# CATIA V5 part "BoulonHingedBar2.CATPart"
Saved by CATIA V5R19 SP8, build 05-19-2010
Part number: BoulonHingedBar2
Bounding box of the stored display mesh (mm): x -36 to 32, y 992 to 1008, z 492 to 508
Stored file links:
  G:\EU_thinkMotion\CFAO_2010\MMS_groupe3\MMS_groupe3\A reprendre\fovide\fovide\BoulonHingedBar2.CATPart
  C:\Users\Rodger\Desktop\Part11.CATPart
  G:\EU_thinkMotion\CFAO_2010\MMS_groupe3\MMS_groupe3\A reprendre\fovide\fovide\fovide.CATProduct
  G:\EU_thinkMotion\CFAO_2010\MMS_groupe3\MMS_groupe3\A reprendre\fovide\fovide\Hinged Bar 15.CATPart
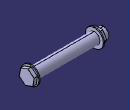
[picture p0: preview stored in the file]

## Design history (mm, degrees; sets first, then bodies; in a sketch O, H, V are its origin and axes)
Parameters
  Diametre = 10 mm
  Longueur = 56 mm
Set1
  DatumSurface1: linked copy from another document
  Point1: linked copy from another document
Body1 (main body)
Body2
  Sketch1 on DatumSurface1, origin (28, 0, 28), H (0, 0, -1), V (0, 1, 0)
    circle A1 centre (-472, 1000) radius 8
    point P1 (-472, 1000)
    reference projected point E1 (-472, 1000) from Point1
    radius A1 = 8 {= Diametre *8/10}
    coincidence: P1 E1
  Pad1: profile Sketch1, direction (1, 0, 0), length 1
  Sketch2 on end face of Pad1, origin (29, 0, 30), H (0, 0, -1), V (0, 1, 0)
    point P1 (-470, 1000)
    point P2 (-467.5061, 993.4593)
    point P3 (-463.0887, 998.8894)
    point P4 (-465.5825, 1005.4301)
    point P5 (-472.4939, 1006.5407)
    point P6 (-476.9113, 1001.1106)
    point P7 (-474.4175, 994.5699)
    point P8 (-465.2974, 996.1744)
    line L1 (-467.5061, 993.4593) -> (-463.0887, 998.8894)
    line L2 (-463.0887, 998.8894) -> (-465.5825, 1005.4301)
    line L3 (-465.5825, 1005.4301) -> (-472.4939, 1006.5407)
    line L4 (-472.4939, 1006.5407) -> (-476.9113, 1001.1106)
    line L5 (-476.9113, 1001.1106) -> (-474.4175, 994.5699)
    line L6 (-474.4175, 994.5699) -> (-467.5061, 993.4593)
    construction line L7 (-470, 1000) -> (-465.2974, 996.1744)
    construction circle A1 centre (-470, 1000) radius 7
    construction arc A2 centre (-476.9113, 1001.1106) radius 7 from (-472.4939, 1006.5407) to (-474.4175, 994.5699) cw
    construction arc A3 centre (-463.0887, 998.8894) radius 7 from (-465.5825, 1005.4301) to (-467.5061, 993.4593) ccw
    reference projected point E1 (-470, 1000) from Point1
    radius A1 = 7 {= Diametre *7/10}
    coincidence: A1 P2, A1 P3, A1 P4, A1 P5, A1 P6, A1 P7, A2 P1, A3 P1, P1 E1
    midpoint: P8 L1
    parallelism: L1 L4
  Pad2: profile Sketch2, direction (1, 0, 0), length 3
  Sketch3 on start face of Pad1, origin (28, 0, 28), H (0, 0, -1), V (0, -1, 0)
    circle A1 centre (-472, -1000) radius 5
    point P1 (-472, -1000)
    reference projected point E1 (-472, -1000) from Point1
    radius A1 = 5 {= Diametre /2}
    coincidence: P1 E1
  Pad3: profile Sketch3, direction (-1, 0, 0), length 56 {= Longueur}
  Sketch4 on end face of Pad3, origin (-28, 0, -52), H (0, 0, -1), V (0, -1, 0)
    circle A1 centre (-552, -1000) radius 8
    point P1 (-552, -1000)
    reference projected point E1 (-552, -1000) from Point1
    radius A1 = 8 {= Diametre *8/10}
    coincidence: P1 E1
  Pad4: profile Sketch4, direction (-1, 0, 0), length 1
  Sketch5 on end face of Pad4, origin (-29, 0, -54), H (0, 0, -1), V (0, -1, 0)
    point P1 (-554, -1000)
    point P2 (-554.0478, -1006.9998)
    point P3 (-547.9619, -1003.5413)
    point P4 (-547.9141, -996.5415)
    point P5 (-553.9522, -993.0002)
    point P6 (-560.0381, -996.4587)
    point P7 (-560.0859, -1003.4585)
    point P8 (-551.0048, -1005.2706)
    line L1 (-554.0478, -1006.9998) -> (-547.9619, -1003.5413)
    line L2 (-547.9619, -1003.5413) -> (-547.9141, -996.5415)
    line L3 (-547.9141, -996.5415) -> (-553.9522, -993.0002)
    line L4 (-553.9522, -993.0002) -> (-560.0381, -996.4587)
    line L5 (-560.0381, -996.4587) -> (-560.0859, -1003.4585)
    line L6 (-560.0859, -1003.4585) -> (-554.0478, -1006.9998)
    construction line L7 (-554, -1000) -> (-551.0048, -1005.2706)
    construction circle A1 centre (-554, -1000) radius 7
    construction arc A2 centre (-560.0381, -996.4587) radius 7 from (-553.9522, -993.0002) to (-560.0859, -1003.4585) cw
    construction arc A3 centre (-547.9619, -1003.5413) radius 7 from (-547.9141, -996.5415) to (-554.0478, -1006.9998) ccw
    reference projected point E1 (-554, -1000) from Point1
    radius A1 = 7 {= Diametre *7/10}
    coincidence: A1 P2, A1 P3, A1 P4, A1 P5, A1 P6, A1 P7, A2 P1, A3 P1, P1 E1
    midpoint: P8 L1
    parallelism: L1 L4
  Pad5: profile Sketch5, direction (-1, 0, 0), length 3
  Sketch6 on end face of Pad5, origin (-32, 0, -60), H (0, 0, -1), V (0, -1, 0)
    circle A1 centre (-560, -1000) radius 5
    point P1 (-560, -1000)
    reference projected point E1 (-560, -1000) from Point1
    radius A1 = 5 {= Diametre /2}
    coincidence: P1 E1
  Pad6: profile Sketch6, direction (-1, 0, 0), length 4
